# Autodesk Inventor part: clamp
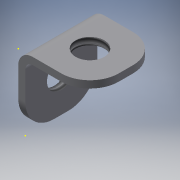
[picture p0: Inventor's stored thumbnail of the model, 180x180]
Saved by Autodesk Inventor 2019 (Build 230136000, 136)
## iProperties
Created: 2020-03
Part Number: clamp
Material: Generic
Document SubType Name: Sheet Metal
Designer: ash
Density: 1 g/cm^3
Sheet Metal Rule: Default_mm
Appearance: Default
Author: ash
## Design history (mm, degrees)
node "Face1"
  sketch "Sketch1"
    geometry: L1 (0, 0)-(5, 0); L2 (5, 0)-(5, -5); L3 (5, -5)-(0, -5); L4 (0, -5)-(0, 0)
    constraints: 8 end point, 2 parallel, 1 horizontal, 1 perpendicular
    dimensions: "d0" = 5 distance of L2.end L3.end; "d1" = 5 distance of L1.end L2.end
node "Flange1"
sketch "Sketch3"
  geometry: L1 (-4, 5)-(0, 5) reference; L2 (0, 5)-(0, 0) reference; 2 further points
  dimensions: "d20" = 2.5 distance from line of L1 point (-2.5, 2.5); "d21" = 2.5 distance from line of L2 point (-2.5, 2.5)
hole "Hole1" sketch "Sketch3" at (-2.5, 2.5) diameter "d13" = 2; stored, may be unused: countersink angle "d17" = 90 deg, drill point angle "d19" = 118 deg; dims "d14" = 6, "d15" = 4, "d16" = 2, "d18" = 0.5 (= Thickness)
sketch "Sketch4"
  geometry: L1 (-5, 0)-(0, 0) reference; L2 (0, 0)-(0, 4) reference; 1 further point
  dimensions: "d22" = 2.5 distance from line of L1 point (-2.5, 2.5); "d23" = 2.5 distance from line of L2 point (-2.5, 2.5)
hole "Hole2" sketch "Sketch4" at (-2.5, 2.5) diameter "d24" = 2; stored, may be unused: countersink angle "d28" = 90 deg, drill point angle "d30" = 118 deg; dims "d25" = 6, "d26" = 4, "d27" = 2, "d29" = 0.5 (= Thickness)
fillet "Fillet1" dims "d31" = 2
thread "Thread1" dims "d32" = 10, "d33" = 0
thread "Thread2" dims "d34" = 10, "d35" = 0
sketch "Sketch5"
  geometry: 1 further point
sketch "Sketch6"
  geometry: 1 further point
sketch "Sketch7"
  geometry: 1 further point
body "Solid1"
face "Plate1" dims "d2" = 0.5 (= Thickness)
sketch "Sketch2"
  geometry: L1 through (0, -2.5) direction (2.72e-32, 1); L2 through (-2.5, 0) direction (-1, 2.54e-33); L3 (-5, 0)-(-5, -5); L4 (-5, -5)-(0, -5)
  constraints: 6 end point, 1 horizontal, 1 perpendicular, 1 vertical
face "Plate2" dims "d2" = 0.5 (= Thickness), "d3" = 0.5 (= BendReliefWidth), "d4" = 0.25 (= BendReliefDepth), "d5" = 1 (= MinimumRemnant), "d6" = 0.5 (= TransitionRadius), "d7" = 5, "d8" = 90 deg, "d9" = 0.5 (= BendRadius), "d10" = 2 (= CornerReliefSize), "d11" = 0.5 (= GapSize), "d12" = 0.5 (= JacobiRadiusSize), "SeamGap" = 0.01
bend "Bend1" dims "d2" = 0.5 (= Thickness), "d3" = 0.5 (= BendReliefWidth), "d4" = 0.25 (= BendReliefDepth), "d5" = 1 (= MinimumRemnant), "d6" = 0.5 (= TransitionRadius), "d7" = 5, "d8" = 90 deg, "d9" = 0.5 (= BendRadius), "SeamGap" = 0.01
feature "Corner1" dims "d7" = 5, "d8" = 90 deg, "d10" = 2 (= CornerReliefSize), "d11" = 0.5 (= GapSize), "d12" = 0.5 (= JacobiRadiusSize)
other parameters: "Thickness" = 0.5, "BendRadius" = 0.5 (= Thickness), "BendReliefWidth" = 0.5 (= Thickness), "BendReliefDepth" = 0.25 (= 0.5 x Thickness), "CornerReliefSize" = 2 (= 4 x Thickness), "MinimumRemnant" = 1 (= 2 x Thickness), "TransitionRadius" = 0.5 (= BendRadius), "JacobiRadiusSize" = 0.5 (= BendRadius), "GapSize" = 0.5 (= Thickness)
